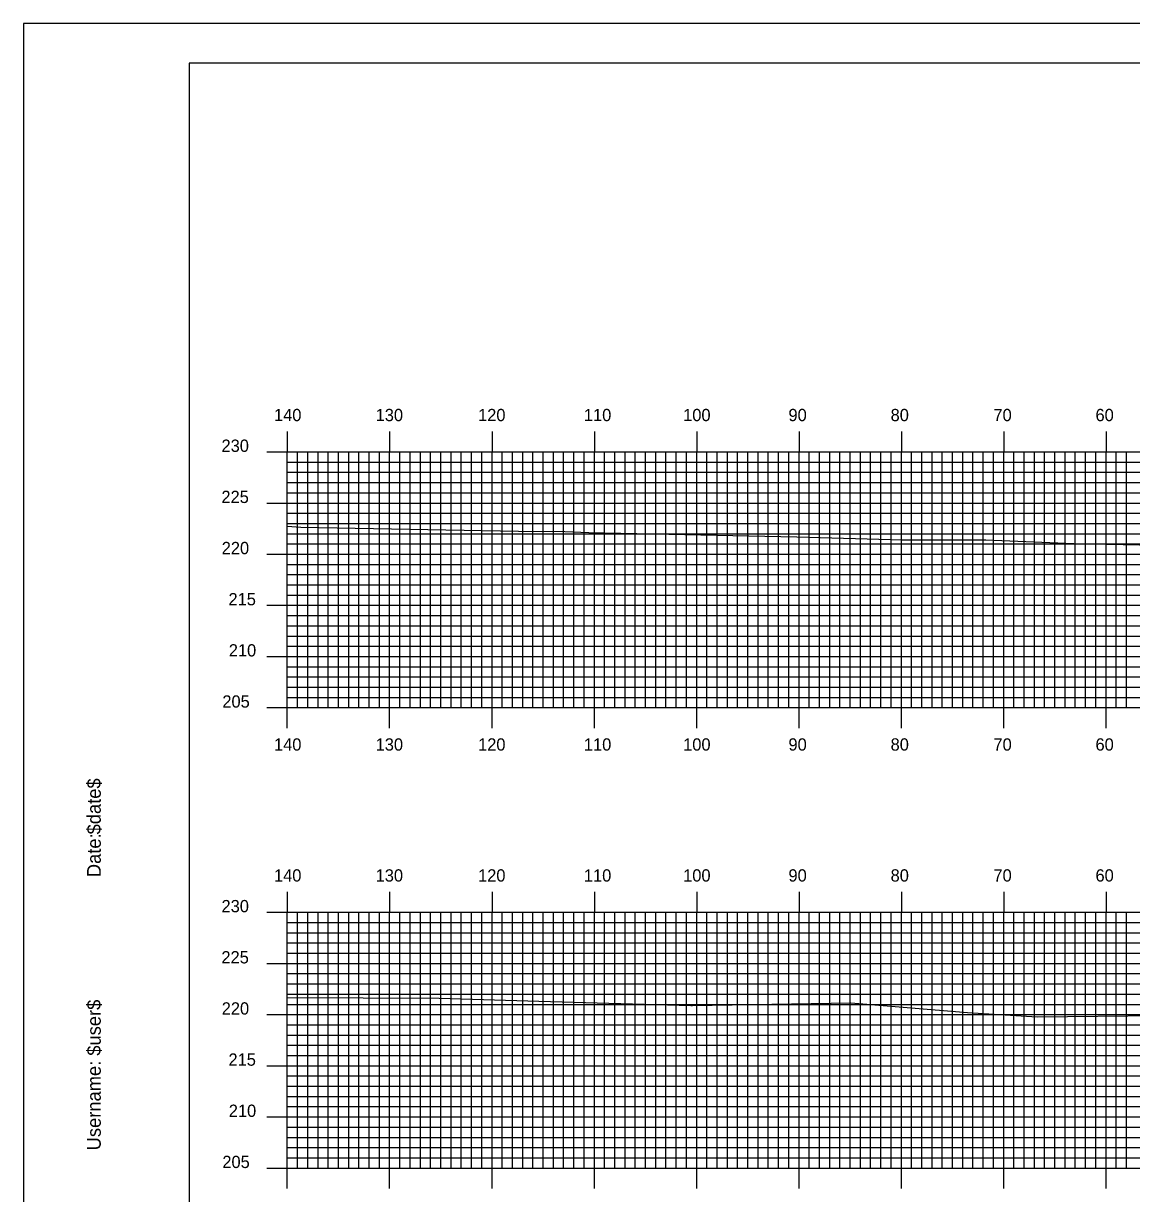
# Model space of a CAD drawing. Extents: x 1819637 to 1819981, y 442591 to 442811.
# Drawn here: x 1819637.4 to 1819745.7, y 442696.2 to 442810.5 of the extents above; entities that cross this region are included whole.
import ezdxf

# ---------------------------------------------------------------- set-up
doc = ezdxf.new("R2010")
doc.units = 0
for name, color, linetype in [('BORDER', 7, 'Continuous'), ('H_V ANNOTATION', 7, 'Continuous'), ('MAJOR', 7, 'Continuous'), ('MINOR', 7, 'Continuous'), ('PLOT BOUNDARY', 7, 'Continuous'), ('S_Roadway_Centerline', 7, 'Continuous')]:
    doc.layers.add(name, color=color, linetype=linetype)

msp = doc.modelspace()

# ---------------------------------------------------------------- linework, layer by layer
at = {"layer": 'BORDER'}
msp.add_lwpolyline([(1819653.58, 442596.67), (1819973.58, 442596.67), (1819973.58, 442806.67), (1819653.58, 442806.67)], close=True, dxfattribs=at)
at = {"layer": 'MAJOR'}
for p, q in [((1819663.18, 442770.67), (1819663.18, 442768.67)), ((1819673.18, 442770.67), (1819673.18, 442768.67)), ((1819683.18, 442770.67), (1819683.18, 442768.67)), ((1819693.18, 442770.67), (1819693.18, 442768.67)), ((1819703.18, 442770.67), (1819703.18, 442768.67)), ((1819713.18, 442770.67), (1819713.18, 442768.67)), ((1819723.18, 442770.67), (1819723.18, 442768.67)), ((1819733.18, 442770.67), (1819733.18, 442768.67)), ((1819743.18, 442770.67), (1819743.18, 442768.67)), ((1819661.17, 442768.67), (1819663.18, 442768.67)), ((1819663.18, 442768.67), (1819943.18, 442768.67)), ((1819663.18, 442743.67), (1819663.18, 442768.67)), ((1819663.18, 442743.67), (1819663.18, 442768.67)), ((1819663.18, 442768.67), (1819943.18, 442768.67)), ((1819673.18, 442743.67), (1819673.18, 442768.67)), ((1819683.18, 442743.67), (1819683.18, 442768.67)), ((1819693.18, 442743.67), (1819693.18, 442768.67)), ((1819703.18, 442743.67), (1819703.18, 442768.67)), ((1819713.18, 442743.67), (1819713.18, 442768.67)), ((1819723.18, 442743.67), (1819723.18, 442768.67)), ((1819733.18, 442743.67), (1819733.18, 442768.67)), ((1819743.18, 442743.67), (1819743.18, 442768.67)), ((1819661.17, 442763.67), (1819663.18, 442763.67)), ((1819663.18, 442763.67), (1819943.18, 442763.67)), ((1819661.17, 442758.67), (1819663.18, 442758.67)), ((1819663.18, 442758.67), (1819943.18, 442758.67)), ((1819661.17, 442753.67), (1819663.18, 442753.67)), ((1819663.18, 442753.67), (1819943.18, 442753.67)), ((1819661.17, 442748.67), (1819663.18, 442748.67)), ((1819663.18, 442748.67), (1819943.18, 442748.67)), ((1819661.17, 442743.67), (1819663.18, 442743.67)), ((1819663.18, 442743.67), (1819943.18, 442743.67)), ((1819663.18, 442743.67), (1819943.18, 442743.67)), ((1819663.18, 442741.66), (1819663.18, 442743.67)), ((1819673.18, 442741.66), (1819673.18, 442743.67)), ((1819683.18, 442741.66), (1819683.18, 442743.67)), ((1819693.18, 442741.66), (1819693.18, 442743.67)), ((1819703.18, 442741.66), (1819703.18, 442743.67)), ((1819713.18, 442741.66), (1819713.18, 442743.67)), ((1819723.18, 442741.66), (1819723.18, 442743.67)), ((1819733.18, 442741.66), (1819733.18, 442743.67)), ((1819743.18, 442741.66), (1819743.18, 442743.67)), ((1819663.18, 442725.67), (1819663.18, 442723.67)), ((1819673.18, 442725.67), (1819673.18, 442723.67)), ((1819683.18, 442725.67), (1819683.18, 442723.67)), ((1819693.18, 442725.67), (1819693.18, 442723.67)), ((1819703.18, 442725.67), (1819703.18, 442723.67)), ((1819713.18, 442725.67), (1819713.18, 442723.67)), ((1819723.18, 442725.67), (1819723.18, 442723.67)), ((1819733.18, 442725.67), (1819733.18, 442723.67)), ((1819743.18, 442725.67), (1819743.18, 442723.67)), ((1819661.17, 442723.67), (1819663.18, 442723.67)), ((1819663.18, 442723.67), (1819943.18, 442723.67)), ((1819663.18, 442698.67), (1819663.18, 442723.67)), ((1819663.18, 442698.67), (1819663.18, 442723.67)), ((1819663.18, 442723.67), (1819943.18, 442723.67)), ((1819673.18, 442698.67), (1819673.18, 442723.67)), ((1819683.18, 442698.67), (1819683.18, 442723.67)), ((1819693.18, 442698.67), (1819693.18, 442723.67)), ((1819703.18, 442698.67), (1819703.18, 442723.67)), ((1819713.18, 442698.67), (1819713.18, 442723.67)), ((1819723.18, 442698.67), (1819723.18, 442723.67)), ((1819733.18, 442698.67), (1819733.18, 442723.67)), ((1819743.18, 442698.67), (1819743.18, 442723.67)), ((1819661.17, 442718.67), (1819663.18, 442718.67)), ((1819663.18, 442718.67), (1819943.18, 442718.67)), ((1819661.17, 442713.67), (1819663.18, 442713.67)), ((1819663.18, 442713.67), (1819943.18, 442713.67)), ((1819661.17, 442708.67), (1819663.18, 442708.67)), ((1819663.18, 442708.67), (1819943.18, 442708.67)), ((1819661.17, 442703.67), (1819663.18, 442703.67)), ((1819663.18, 442703.67), (1819943.18, 442703.67)), ((1819661.17, 442698.67), (1819663.18, 442698.67)), ((1819663.18, 442698.67), (1819943.18, 442698.67)), ((1819663.18, 442698.67), (1819943.18, 442698.67)), ((1819663.18, 442696.66), (1819663.18, 442698.67)), ((1819673.18, 442696.66), (1819673.18, 442698.67)), ((1819683.18, 442696.66), (1819683.18, 442698.67)), ((1819693.18, 442696.66), (1819693.18, 442698.67)), ((1819703.18, 442696.66), (1819703.18, 442698.67)), ((1819713.18, 442696.66), (1819713.18, 442698.67)), ((1819723.18, 442696.66), (1819723.18, 442698.67)), ((1819733.18, 442696.66), (1819733.18, 442698.67)), ((1819743.18, 442696.66), (1819743.18, 442698.67))]:
    msp.add_line(p, q, dxfattribs=at)
at = {"layer": 'MINOR'}
for p, q in [((1819663.18, 442767.67), (1819943.18, 442767.67)), ((1819663.18, 442767.67), (1819665.18, 442767.67)), ((1819664.18, 442743.67), (1819664.18, 442768.67)), ((1819665.18, 442743.67), (1819665.18, 442768.67)), ((1819666.18, 442743.67), (1819666.18, 442768.67)), ((1819667.18, 442743.67), (1819667.18, 442768.67)), ((1819668.18, 442743.67), (1819668.18, 442768.67)), ((1819669.18, 442743.67), (1819669.18, 442768.67)), ((1819670.18, 442743.67), (1819670.18, 442768.67)), ((1819671.18, 442743.67), (1819671.18, 442768.67)), ((1819672.18, 442743.67), (1819672.18, 442768.67)), ((1819674.18, 442743.67), (1819674.18, 442768.67)), ((1819675.18, 442743.67), (1819675.18, 442768.67)), ((1819676.18, 442743.67), (1819676.18, 442768.67)), ((1819677.18, 442743.67), (1819677.18, 442768.67)), ((1819678.18, 442743.67), (1819678.18, 442768.67)), ((1819679.18, 442743.67), (1819679.18, 442768.67)), ((1819680.18, 442743.67), (1819680.18, 442768.67)), ((1819681.18, 442743.67), (1819681.18, 442768.67)), ((1819682.18, 442743.67), (1819682.18, 442768.67)), ((1819684.18, 442743.67), (1819684.18, 442768.67)), ((1819685.18, 442743.67), (1819685.18, 442768.67)), ((1819686.18, 442743.67), (1819686.18, 442768.67)), ((1819687.18, 442743.67), (1819687.18, 442768.67)), ((1819688.18, 442743.67), (1819688.18, 442768.67)), ((1819689.18, 442743.67), (1819689.18, 442768.67)), ((1819690.18, 442743.67), (1819690.18, 442768.67)), ((1819691.18, 442743.67), (1819691.18, 442768.67)), ((1819692.18, 442743.67), (1819692.18, 442768.67)), ((1819694.18, 442743.67), (1819694.18, 442768.67)), ((1819695.18, 442743.67), (1819695.18, 442768.67)), ((1819696.18, 442743.67), (1819696.18, 442768.67)), ((1819697.18, 442743.67), (1819697.18, 442768.67)), ((1819698.18, 442743.67), (1819698.18, 442768.67)), ((1819699.18, 442743.67), (1819699.18, 442768.67)), ((1819700.18, 442743.67), (1819700.18, 442768.67)), ((1819701.18, 442743.67), (1819701.18, 442768.67)), ((1819702.18, 442743.67), (1819702.18, 442768.67)), ((1819704.18, 442743.67), (1819704.18, 442768.67)), ((1819705.18, 442743.67), (1819705.18, 442768.67)), ((1819706.18, 442743.67), (1819706.18, 442768.67)), ((1819707.18, 442743.67), (1819707.18, 442768.67)), ((1819708.18, 442743.67), (1819708.18, 442768.67)), ((1819709.18, 442743.67), (1819709.18, 442768.67)), ((1819710.18, 442743.67), (1819710.18, 442768.67)), ((1819711.18, 442743.67), (1819711.18, 442768.67)), ((1819712.18, 442743.67), (1819712.18, 442768.67)), ((1819714.18, 442743.67), (1819714.18, 442768.67)), ((1819715.18, 442743.67), (1819715.18, 442768.67)), ((1819716.18, 442743.67), (1819716.18, 442768.67)), ((1819717.18, 442743.67), (1819717.18, 442768.67)), ((1819718.18, 442743.67), (1819718.18, 442768.67)), ((1819719.18, 442743.67), (1819719.18, 442768.67)), ((1819720.18, 442743.67), (1819720.18, 442768.67)), ((1819721.18, 442743.67), (1819721.18, 442768.67)), ((1819722.18, 442743.67), (1819722.18, 442768.67)), ((1819724.18, 442743.67), (1819724.18, 442768.67)), ((1819725.18, 442743.67), (1819725.18, 442768.67)), ((1819726.18, 442743.67), (1819726.18, 442768.67)), ((1819727.18, 442743.67), (1819727.18, 442768.67)), ((1819728.18, 442743.67), (1819728.18, 442768.67)), ((1819729.18, 442743.67), (1819729.18, 442768.67)), ((1819730.18, 442743.67), (1819730.18, 442768.67)), ((1819731.18, 442743.67), (1819731.18, 442768.67)), ((1819732.18, 442743.67), (1819732.18, 442768.67)), ((1819734.18, 442743.67), (1819734.18, 442768.67)), ((1819735.18, 442743.67), (1819735.18, 442768.67)), ((1819736.18, 442743.67), (1819736.18, 442768.67)), ((1819737.18, 442743.67), (1819737.18, 442768.67)), ((1819738.18, 442743.67), (1819738.18, 442768.67)), ((1819739.18, 442743.67), (1819739.18, 442768.67)), ((1819740.18, 442743.67), (1819740.18, 442768.67)), ((1819741.18, 442743.67), (1819741.18, 442768.67)), ((1819742.18, 442743.67), (1819742.18, 442768.67)), ((1819744.18, 442743.67), (1819744.18, 442768.67)), ((1819745.18, 442743.67), (1819745.18, 442768.67)), ((1819663.18, 442766.67), (1819943.18, 442766.67)), ((1819663.18, 442766.67), (1819665.18, 442766.67)), ((1819663.18, 442765.67), (1819943.18, 442765.67)), ((1819663.18, 442765.67), (1819665.18, 442765.67)), ((1819663.18, 442764.67), (1819943.18, 442764.67)), ((1819663.18, 442764.67), (1819665.18, 442764.67)), ((1819663.18, 442762.67), (1819943.18, 442762.67)), ((1819663.18, 442762.67), (1819665.18, 442762.67)), ((1819663.18, 442761.67), (1819943.18, 442761.67)), ((1819663.18, 442761.67), (1819665.18, 442761.67)), ((1819663.18, 442760.67), (1819943.18, 442760.67)), ((1819663.18, 442760.67), (1819665.18, 442760.67)), ((1819663.18, 442759.67), (1819943.18, 442759.67)), ((1819663.18, 442759.67), (1819665.18, 442759.67)), ((1819663.18, 442757.67), (1819943.18, 442757.67)), ((1819663.18, 442757.67), (1819665.18, 442757.67)), ((1819663.18, 442756.67), (1819943.18, 442756.67)), ((1819663.18, 442756.67), (1819665.18, 442756.67)), ((1819663.18, 442755.67), (1819943.18, 442755.67)), ((1819663.18, 442755.67), (1819665.18, 442755.67)), ((1819663.18, 442754.67), (1819943.18, 442754.67)), ((1819663.18, 442754.67), (1819665.18, 442754.67)), ((1819663.18, 442752.67), (1819943.18, 442752.67)), ((1819663.18, 442752.67), (1819665.18, 442752.67)), ((1819663.18, 442751.67), (1819943.18, 442751.67)), ((1819663.18, 442751.67), (1819665.18, 442751.67)), ((1819663.18, 442750.67), (1819943.18, 442750.67)), ((1819663.18, 442750.67), (1819665.18, 442750.67)), ((1819663.18, 442749.67), (1819943.18, 442749.67)), ((1819663.18, 442749.67), (1819665.18, 442749.67)), ((1819663.18, 442747.67), (1819943.18, 442747.67)), ((1819663.18, 442747.67), (1819665.18, 442747.67)), ((1819663.18, 442746.67), (1819943.18, 442746.67)), ((1819663.18, 442746.67), (1819665.18, 442746.67)), ((1819663.18, 442745.67), (1819943.18, 442745.67)), ((1819663.18, 442745.67), (1819665.18, 442745.67)), ((1819663.18, 442744.67), (1819943.18, 442744.67)), ((1819663.18, 442744.67), (1819665.18, 442744.67)), ((1819664.18, 442698.67), (1819664.18, 442723.67)), ((1819665.18, 442698.67), (1819665.18, 442723.67)), ((1819666.18, 442698.67), (1819666.18, 442723.67)), ((1819667.18, 442698.67), (1819667.18, 442723.67)), ((1819668.18, 442698.67), (1819668.18, 442723.67)), ((1819669.18, 442698.67), (1819669.18, 442723.67)), ((1819670.18, 442698.67), (1819670.18, 442723.67)), ((1819671.18, 442698.67), (1819671.18, 442723.67)), ((1819672.18, 442698.67), (1819672.18, 442723.67)), ((1819674.18, 442698.67), (1819674.18, 442723.67)), ((1819675.18, 442698.67), (1819675.18, 442723.67)), ((1819676.18, 442698.67), (1819676.18, 442723.67)), ((1819677.18, 442698.67), (1819677.18, 442723.67)), ((1819678.18, 442698.67), (1819678.18, 442723.67)), ((1819679.18, 442698.67), (1819679.18, 442723.67)), ((1819680.18, 442698.67), (1819680.18, 442723.67)), ((1819681.18, 442698.67), (1819681.18, 442723.67)), ((1819682.18, 442698.67), (1819682.18, 442723.67)), ((1819684.18, 442698.67), (1819684.18, 442723.67)), ((1819685.18, 442698.67), (1819685.18, 442723.67)), ((1819686.18, 442698.67), (1819686.18, 442723.67)), ((1819687.18, 442698.67), (1819687.18, 442723.67)), ((1819688.18, 442698.67), (1819688.18, 442723.67)), ((1819689.18, 442698.67), (1819689.18, 442723.67)), ((1819690.18, 442698.67), (1819690.18, 442723.67)), ((1819691.18, 442698.67), (1819691.18, 442723.67)), ((1819692.18, 442698.67), (1819692.18, 442723.67)), ((1819694.18, 442698.67), (1819694.18, 442723.67)), ((1819695.18, 442698.67), (1819695.18, 442723.67)), ((1819696.18, 442698.67), (1819696.18, 442723.67)), ((1819697.18, 442698.67), (1819697.18, 442723.67)), ((1819698.18, 442698.67), (1819698.18, 442723.67)), ((1819699.18, 442698.67), (1819699.18, 442723.67)), ((1819700.18, 442698.67), (1819700.18, 442723.67)), ((1819701.18, 442698.67), (1819701.18, 442723.67)), ((1819702.18, 442698.67), (1819702.18, 442723.67)), ((1819704.18, 442698.67), (1819704.18, 442723.67)), ((1819705.18, 442698.67), (1819705.18, 442723.67)), ((1819706.18, 442698.67), (1819706.18, 442723.67)), ((1819707.18, 442698.67), (1819707.18, 442723.67)), ((1819708.18, 442698.67), (1819708.18, 442723.67)), ((1819709.18, 442698.67), (1819709.18, 442723.67)), ((1819710.18, 442698.67), (1819710.18, 442723.67)), ((1819711.18, 442698.67), (1819711.18, 442723.67)), ((1819712.18, 442698.67), (1819712.18, 442723.67)), ((1819714.18, 442698.67), (1819714.18, 442723.67)), ((1819715.18, 442698.67), (1819715.18, 442723.67)), ((1819716.18, 442698.67), (1819716.18, 442723.67)), ((1819717.18, 442698.67), (1819717.18, 442723.67)), ((1819718.18, 442698.67), (1819718.18, 442723.67)), ((1819719.18, 442698.67), (1819719.18, 442723.67)), ((1819720.18, 442698.67), (1819720.18, 442723.67)), ((1819721.18, 442698.67), (1819721.18, 442723.67)), ((1819722.18, 442698.67), (1819722.18, 442723.67)), ((1819724.18, 442698.67), (1819724.18, 442723.67)), ((1819725.18, 442698.67), (1819725.18, 442723.67)), ((1819726.18, 442698.67), (1819726.18, 442723.67)), ((1819727.18, 442698.67), (1819727.18, 442723.67)), ((1819728.18, 442698.67), (1819728.18, 442723.67)), ((1819729.18, 442698.67), (1819729.18, 442723.67)), ((1819730.18, 442698.67), (1819730.18, 442723.67)), ((1819731.18, 442698.67), (1819731.18, 442723.67)), ((1819732.18, 442698.67), (1819732.18, 442723.67)), ((1819734.18, 442698.67), (1819734.18, 442723.67)), ((1819735.18, 442698.67), (1819735.18, 442723.67)), ((1819736.18, 442698.67), (1819736.18, 442723.67)), ((1819737.18, 442698.67), (1819737.18, 442723.67)), ((1819738.18, 442698.67), (1819738.18, 442723.67)), ((1819739.18, 442698.67), (1819739.18, 442723.67)), ((1819740.18, 442698.67), (1819740.18, 442723.67)), ((1819741.18, 442698.67), (1819741.18, 442723.67)), ((1819742.18, 442698.67), (1819742.18, 442723.67)), ((1819744.18, 442698.67), (1819744.18, 442723.67)), ((1819745.18, 442698.67), (1819745.18, 442723.67)), ((1819663.18, 442722.67), (1819943.18, 442722.67)), ((1819663.18, 442722.67), (1819665.18, 442722.67)), ((1819663.18, 442721.67), (1819943.18, 442721.67)), ((1819663.18, 442721.67), (1819665.18, 442721.67)), ((1819663.18, 442720.67), (1819943.18, 442720.67)), ((1819663.18, 442720.67), (1819665.18, 442720.67)), ((1819663.18, 442719.67), (1819943.18, 442719.67)), ((1819663.18, 442719.67), (1819665.18, 442719.67)), ((1819663.18, 442717.67), (1819943.18, 442717.67)), ((1819663.18, 442717.67), (1819665.18, 442717.67)), ((1819663.18, 442716.67), (1819943.18, 442716.67)), ((1819663.18, 442716.67), (1819665.18, 442716.67)), ((1819663.18, 442715.67), (1819943.18, 442715.67)), ((1819663.18, 442715.67), (1819665.18, 442715.67)), ((1819663.18, 442714.67), (1819943.18, 442714.67)), ((1819663.18, 442714.67), (1819665.18, 442714.67)), ((1819663.18, 442712.67), (1819943.18, 442712.67)), ((1819663.18, 442712.67), (1819665.18, 442712.67)), ((1819663.18, 442711.67), (1819943.18, 442711.67)), ((1819663.18, 442711.67), (1819665.18, 442711.67)), ((1819663.18, 442710.67), (1819943.18, 442710.67)), ((1819663.18, 442710.67), (1819665.18, 442710.67)), ((1819663.18, 442709.67), (1819943.18, 442709.67)), ((1819663.18, 442709.67), (1819665.18, 442709.67)), ((1819663.18, 442707.67), (1819943.18, 442707.67)), ((1819663.18, 442707.67), (1819665.18, 442707.67)), ((1819663.18, 442706.67), (1819943.18, 442706.67)), ((1819663.18, 442706.67), (1819665.18, 442706.67)), ((1819663.18, 442705.67), (1819943.18, 442705.67)), ((1819663.18, 442705.67), (1819665.18, 442705.67)), ((1819663.18, 442704.67), (1819943.18, 442704.67)), ((1819663.18, 442704.67), (1819665.18, 442704.67)), ((1819663.18, 442702.67), (1819943.18, 442702.67)), ((1819663.18, 442702.67), (1819665.18, 442702.67)), ((1819663.18, 442701.67), (1819943.18, 442701.67)), ((1819663.18, 442701.67), (1819665.18, 442701.67)), ((1819663.18, 442700.67), (1819943.18, 442700.67)), ((1819663.18, 442700.67), (1819665.18, 442700.67)), ((1819663.18, 442699.67), (1819943.18, 442699.67)), ((1819663.18, 442699.67), (1819665.18, 442699.67))]:
    msp.add_line(p, q, dxfattribs=at)
at = {"layer": 'PLOT BOUNDARY'}
msp.add_lwpolyline([(1819637.39, 442590.55), (1819977.39, 442590.55), (1819977.39, 442810.55), (1819637.39, 442810.55)], close=True, dxfattribs=at)
at = {"layer": 'S_Roadway_Centerline'}
for points in [[(1819663.18, 442761.42), (1819664.51, 442761.32), (1819685.77, 442760.93), (1819690.3, 442760.87), (1819692.65, 442760.78), (1819712.98, 442760.35), (1819723.25, 442760.08), (1819731.45, 442760.07), (1819740.05, 442759.71), (1819754.45, 442759.43), (1819756.64, 442759.29), (1819757.97, 442759.28), (1819765.44, 442758.81), (1819771.89, 442758.41), (1819772.54, 442758.34), (1819774.6, 442758.21), (1819789.59, 442757.21), (1819802.74, 442756.39), (1819811.49, 442755.85), (1819833.95, 442755.43), (1819841.85, 442755.26), (1819859.26, 442754.92)], [(1819663.18, 442715.35), (1819678.01, 442715.26), (1819687.76, 442714.98), (1819702.62, 442714.56), (1819702.72, 442714.55), (1819702.76, 442714.55), (1819718.24, 442714.82), (1819729.65, 442713.88), (1819736.46, 442713.45), (1819748.29, 442713.59), (1819752.75, 442713.37), (1819755.34, 442713.49), (1819766.13, 442712.68), (1819769.16, 442712.46), (1819769.93, 442712.42), (1819771.13, 442712.34), (1819787.25, 442711.42), (1819793.12, 442711.25), (1819812.84, 442710.11), (1819846.2, 442710), (1819849.54, 442709.93), (1819854.82, 442709.66)]]:
    msp.add_lwpolyline(points, dxfattribs=at)

# ---------------------------------------------------------------- texts
at = {"layer": 'BORDER'}
for s, p in [('$date$', (1819644.95, 442731.28)), ('Date:', (1819644.95, 442727.1)), ('$user$', (1819644.95, 442709.65)), ('Username:', (1819644.95, 442700.4))]:
    msp.add_text(s, height=1.339, rotation=90, dxfattribs=at).set_placement(p)
at = {"layer": 'H_V ANNOTATION'}
for s, p in [('140', (1819661.88, 442771.67)), ('130', (1819671.81, 442771.67)), ('120', (1819681.82, 442771.67)), ('110', (1819692.16, 442771.67)), ('100', (1819701.86, 442771.67)), ('90', (1819712.15, 442771.67)), ('80', (1819722.13, 442771.67)), ('70', (1819732.18, 442771.67)), ('60', (1819742.15, 442771.67)), ('230', (1819656.75, 442768.67)), ('225', (1819656.74, 442763.67)), ('220', (1819656.77, 442758.67)), ('215', (1819657.43, 442753.67)), ('210', (1819657.46, 442748.67)), ('205', (1819656.83, 442743.67)), ('140', (1819661.88, 442739.47)), ('130', (1819671.81, 442739.47)), ('120', (1819681.82, 442739.47)), ('110', (1819692.16, 442739.47)), ('100', (1819701.86, 442739.47)), ('90', (1819712.15, 442739.47)), ('80', (1819722.13, 442739.47)), ('70', (1819732.18, 442739.47)), ('60', (1819742.15, 442739.47)), ('140', (1819661.88, 442726.67)), ('130', (1819671.81, 442726.67)), ('120', (1819681.82, 442726.67)), ('110', (1819692.16, 442726.67)), ('100', (1819701.86, 442726.67)), ('90', (1819712.15, 442726.67)), ('80', (1819722.13, 442726.67)), ('70', (1819732.18, 442726.67)), ('60', (1819742.15, 442726.67)), ('230', (1819656.75, 442723.67)), ('225', (1819656.74, 442718.67)), ('220', (1819656.77, 442713.67)), ('215', (1819657.43, 442708.67)), ('210', (1819657.46, 442703.67)), ('205', (1819656.83, 442698.67))]:
    msp.add_text(s, height=1.2, dxfattribs=at).set_placement(p)
at = {"layer": 'MAJOR'}
for p in [(1819663.17, 442743.67), (1819663.17, 442698.67)]:
    msp.add_text('-', height=0.012, dxfattribs=at).set_placement(p)

doc.saveas('drawing.dxf')
